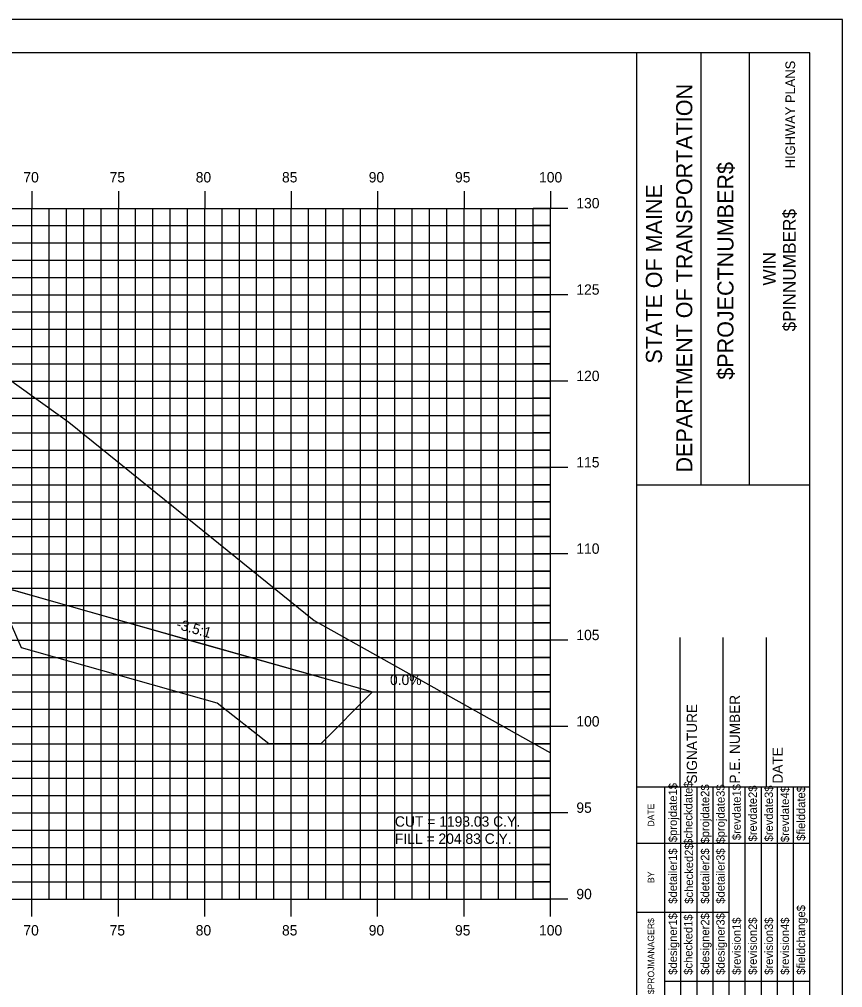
# Model space of a CAD drawing. Extents: x 850598 to 870284, y 366541 to 366651.
# Drawn here: x 854268.3 to 854315.9, y 366595.1 to 366651.2 of the extents above; entities that cross this region are included whole.
import ezdxf

# ---------------------------------------------------------------- set-up
doc = ezdxf.new("R2010")
doc.units = 0
for name, color, linetype in [('ANNOTATION', 7, 'Continuous'), ('BORDER', 7, 'Continuous'), ('D_Drainage_RipRap', 7, 'Continuous'), ('D_Roadway_Centerline', 7, 'Continuous'), ('D_Roadway_SlopeLines', 7, 'Continuous'), ('D_Text_Standard', 7, 'Continuous'), ('H_V ANNOTATION', 7, 'Continuous'), ('HIGHWAY_TITLE', 7, 'Continuous'), ('MAJOR', 7, 'Continuous'), ('MINOR', 7, 'Continuous'), ('PLOT BOUNDARY', 7, 'Continuous'), ('S_Roadway_Centerline', 7, 'Continuous')]:
    doc.layers.add(name, color=color, linetype=linetype)

msp = doc.modelspace()

# ---------------------------------------------------------------- linework, layer by layer
at = {"layer": 'BORDER'}
for p, q in [((854314.002, 366649.225), (854154.002, 366649.225)), ((854304.002, 366544.225), (854304.002, 366649.225)), ((854307.73, 366624.222), (854307.73, 366649.222)), ((854310.525, 366624.222), (854310.525, 366649.222)), ((854314.002, 366544.225), (854314.002, 366649.225)), ((854304.003, 366624.219), (854314.002, 366624.219)), ((854306.502, 366606.728), (854306.502, 366615.376)), ((854309.002, 366606.728), (854309.002, 366615.376)), ((854311.502, 366606.728), (854311.502, 366615.376)), ((854304.002, 366606.728), (854314.002, 366606.728))]:
    msp.add_line(p, q, dxfattribs=at)
for points in [[(854305.617, 366603.478), (854305.617, 366606.728)], [(854306.549, 366589.231), (854306.549, 366606.728)], [(854307.481, 366606.728), (854307.481, 366589.231)], [(854308.413, 366589.231), (854308.413, 366606.728)], [(854309.344, 366589.231), (854309.344, 366606.728)], [(854310.276, 366589.231), (854310.276, 366606.728)], [(854311.208, 366589.231), (854311.208, 366606.728)], [(854312.139, 366589.231), (854312.139, 366606.728)], [(854313.071, 366589.231), (854313.071, 366606.728)], [(854305.618, 366589.231), (854305.618, 366606.022)], [(854304.002, 366603.478), (854314.002, 366603.478)], [(854304.002, 366599.478), (854305.618, 366599.478)], [(854305.617, 366599.478), (854309.343, 366599.478)], [(854305.617, 366595.478), (854314.002, 366595.478)]]:
    msp.add_lwpolyline(points, dxfattribs=at)
at = {"layer": 'D_Drainage_RipRap'}
msp.add_lwpolyline([(854267.538, 366618.225), (854278.852, 366615.02), (854288.714, 366612.225), (854285.714, 366609.225), (854282.714, 366609.225), (854279.714, 366611.57), (854268.4, 366614.775), (854267.538, 366616.725), (854222.002, 366629.628), (854222.002, 366631.128)], close=True, dxfattribs=at)
at = {"layer": 'D_Roadway_Centerline'}
msp.add_lwpolyline([(854168.892, 366628.211), (854174.002, 366629.914), (854177.804, 366631.182), (854184.002, 366633.248), (854188.002, 366633.488), (854199.002, 366633.818), (854210.002, 366633.488), (854214.002, 366633.248), (854216.002, 366633.128), (854222.002, 366631.128), (854267.538, 366618.225), (854278.852, 366615.02), (854288.714, 366612.225), (854292.714, 366612.225)], dxfattribs=at)
at = {"layer": 'D_Roadway_SlopeLines'}
msp.add_lwpolyline([(854222.002, 366631.128), (854288.714, 366612.225), (854288.714, 366612.225)], dxfattribs=at)
at = {"layer": 'MAJOR'}
for p, q in [((854269.002, 366641.227), (854269.002, 366640.225)), ((854269.002, 366641.227), (854269.002, 366640.225)), ((854274.002, 366641.227), (854274.002, 366640.225)), ((854274.002, 366641.227), (854274.002, 366640.225)), ((854279.002, 366641.227), (854279.002, 366640.225)), ((854279.002, 366641.227), (854279.002, 366640.225)), ((854284.002, 366641.227), (854284.002, 366640.225)), ((854284.002, 366641.227), (854284.002, 366640.225)), ((854289.002, 366641.227), (854289.002, 366640.225)), ((854289.002, 366641.227), (854289.002, 366640.225)), ((854294.002, 366641.227), (854294.002, 366640.225)), ((854294.002, 366641.227), (854294.002, 366640.225)), ((854299.002, 366641.227), (854299.002, 366640.225)), ((854299.002, 366641.227), (854299.002, 366640.225)), ((854159.002, 366640.225), (854299.002, 366640.225)), ((854159.002, 366640.225), (854299.002, 366640.225)), ((854159.002, 366640.225), (854299.002, 366640.225)), ((854159.002, 366640.225), (854299.002, 366640.225)), ((854269.002, 366600.225), (854269.002, 366640.225)), ((854269.002, 366600.225), (854269.002, 366640.225)), ((854274.002, 366600.225), (854274.002, 366640.225)), ((854274.002, 366600.225), (854274.002, 366640.225)), ((854279.002, 366600.225), (854279.002, 366640.225)), ((854279.002, 366600.225), (854279.002, 366640.225)), ((854284.002, 366600.225), (854284.002, 366640.225)), ((854284.002, 366600.225), (854284.002, 366640.225)), ((854289.002, 366600.225), (854289.002, 366640.225)), ((854289.002, 366600.225), (854289.002, 366640.225)), ((854294.002, 366600.225), (854294.002, 366640.225)), ((854294.002, 366600.225), (854294.002, 366640.225)), ((854300.004, 366640.225), (854298, 366640.225)), ((854300.004, 366640.225), (854298, 366640.225)), ((854299.002, 366600.225), (854299.002, 366640.225)), ((854299.002, 366600.225), (854299.002, 366640.225)), ((854299.002, 366600.225), (854299.002, 366640.225)), ((854299.002, 366600.225), (854299.002, 366640.225)), ((854159.002, 366635.225), (854299.002, 366635.225)), ((854159.002, 366635.225), (854299.002, 366635.225)), ((854300.004, 366635.225), (854298, 366635.225)), ((854300.004, 366635.225), (854298, 366635.225)), ((854159.002, 366630.225), (854299.002, 366630.225)), ((854159.002, 366630.225), (854299.002, 366630.225)), ((854300.004, 366630.225), (854298, 366630.225)), ((854300.004, 366630.225), (854298, 366630.225)), ((854159.002, 366625.225), (854299.002, 366625.225)), ((854159.002, 366625.225), (854299.002, 366625.225)), ((854300.004, 366625.225), (854298, 366625.225)), ((854300.004, 366625.225), (854298, 366625.225)), ((854159.002, 366620.225), (854299.002, 366620.225)), ((854159.002, 366620.225), (854299.002, 366620.225)), ((854300.004, 366620.225), (854298, 366620.225)), ((854300.004, 366620.225), (854298, 366620.225)), ((854159.002, 366615.225), (854299.002, 366615.225)), ((854159.002, 366615.225), (854299.002, 366615.225)), ((854300.004, 366615.225), (854298, 366615.225)), ((854300.004, 366615.225), (854298, 366615.225)), ((854159.002, 366610.225), (854299.002, 366610.225)), ((854159.002, 366610.225), (854299.002, 366610.225)), ((854300.004, 366610.225), (854298, 366610.225)), ((854300.004, 366610.225), (854298, 366610.225)), ((854159.002, 366605.225), (854299.002, 366605.225)), ((854159.002, 366605.225), (854299.002, 366605.225)), ((854300.004, 366605.225), (854298, 366605.225)), ((854300.004, 366605.225), (854298, 366605.225)), ((854159.002, 366600.225), (854299.002, 366600.225)), ((854159.002, 366600.225), (854299.002, 366600.225)), ((854159.002, 366600.225), (854299.002, 366600.225)), ((854159.002, 366600.225), (854299.002, 366600.225)), ((854269.002, 366599.223), (854269.002, 366600.225)), ((854269.002, 366599.223), (854269.002, 366600.225)), ((854274.002, 366599.223), (854274.002, 366600.225)), ((854274.002, 366599.223), (854274.002, 366600.225)), ((854279.002, 366599.223), (854279.002, 366600.225)), ((854279.002, 366599.223), (854279.002, 366600.225)), ((854284.002, 366599.223), (854284.002, 366600.225)), ((854284.002, 366599.223), (854284.002, 366600.225)), ((854289.002, 366599.223), (854289.002, 366600.225)), ((854289.002, 366599.223), (854289.002, 366600.225)), ((854294.002, 366599.223), (854294.002, 366600.225)), ((854294.002, 366599.223), (854294.002, 366600.225)), ((854300.004, 366600.225), (854298, 366600.225)), ((854300.004, 366600.225), (854298, 366600.225)), ((854299.002, 366599.223), (854299.002, 366600.225)), ((854299.002, 366599.223), (854299.002, 366600.225))]:
    msp.add_line(p, q, dxfattribs=at)
at = {"layer": 'MINOR'}
for p, q in [((854270.002, 366600.225), (854270.002, 366640.225)), ((854270.002, 366600.225), (854270.002, 366640.225)), ((854271.002, 366600.225), (854271.002, 366640.225)), ((854271.002, 366600.225), (854271.002, 366640.225)), ((854272.002, 366600.225), (854272.002, 366640.225)), ((854272.002, 366600.225), (854272.002, 366640.225)), ((854273.002, 366600.225), (854273.002, 366640.225)), ((854273.002, 366600.225), (854273.002, 366640.225)), ((854275.002, 366600.225), (854275.002, 366640.225)), ((854275.002, 366600.225), (854275.002, 366640.225)), ((854276.002, 366600.225), (854276.002, 366640.225)), ((854276.002, 366600.225), (854276.002, 366640.225)), ((854277.002, 366600.225), (854277.002, 366640.225)), ((854277.002, 366600.225), (854277.002, 366640.225)), ((854278.002, 366600.225), (854278.002, 366640.225)), ((854278.002, 366600.225), (854278.002, 366640.225)), ((854280.002, 366600.225), (854280.002, 366640.225)), ((854280.002, 366600.225), (854280.002, 366640.225)), ((854281.002, 366600.225), (854281.002, 366640.225)), ((854281.002, 366600.225), (854281.002, 366640.225)), ((854282.002, 366600.225), (854282.002, 366640.225)), ((854282.002, 366600.225), (854282.002, 366640.225)), ((854283.002, 366600.225), (854283.002, 366640.225)), ((854283.002, 366600.225), (854283.002, 366640.225)), ((854285.002, 366600.225), (854285.002, 366640.225)), ((854285.002, 366600.225), (854285.002, 366640.225)), ((854286.002, 366600.225), (854286.002, 366640.225)), ((854286.002, 366600.225), (854286.002, 366640.225)), ((854287.002, 366600.225), (854287.002, 366640.225)), ((854287.002, 366600.225), (854287.002, 366640.225)), ((854288.002, 366600.225), (854288.002, 366640.225)), ((854288.002, 366600.225), (854288.002, 366640.225)), ((854290.002, 366600.225), (854290.002, 366640.225)), ((854290.002, 366600.225), (854290.002, 366640.225)), ((854291.002, 366600.225), (854291.002, 366640.225)), ((854291.002, 366600.225), (854291.002, 366640.225)), ((854292.002, 366600.225), (854292.002, 366640.225)), ((854292.002, 366600.225), (854292.002, 366640.225)), ((854293.002, 366600.225), (854293.002, 366640.225)), ((854293.002, 366600.225), (854293.002, 366640.225)), ((854295.002, 366600.225), (854295.002, 366640.225)), ((854295.002, 366600.225), (854295.002, 366640.225)), ((854296.002, 366600.225), (854296.002, 366640.225)), ((854296.002, 366600.225), (854296.002, 366640.225)), ((854297.002, 366600.225), (854297.002, 366640.225)), ((854297.002, 366600.225), (854297.002, 366640.225)), ((854298.002, 366600.225), (854298.002, 366640.225)), ((854298.002, 366600.225), (854298.002, 366640.225)), ((854159.002, 366639.225), (854299.002, 366639.225)), ((854159.002, 366639.225), (854299.002, 366639.225)), ((854299.002, 366639.225), (854298, 366639.225)), ((854299.002, 366639.225), (854298, 366639.225)), ((854159.002, 366638.225), (854299.002, 366638.225)), ((854159.002, 366638.225), (854299.002, 366638.225)), ((854299.002, 366638.225), (854298, 366638.225)), ((854299.002, 366638.225), (854298, 366638.225)), ((854159.002, 366637.225), (854299.002, 366637.225)), ((854159.002, 366637.225), (854299.002, 366637.225)), ((854299.002, 366637.225), (854298, 366637.225)), ((854299.002, 366637.225), (854298, 366637.225)), ((854159.002, 366636.225), (854299.002, 366636.225)), ((854159.002, 366636.225), (854299.002, 366636.225)), ((854299.002, 366636.225), (854298, 366636.225)), ((854299.002, 366636.225), (854298, 366636.225)), ((854159.002, 366634.225), (854299.002, 366634.225)), ((854159.002, 366634.225), (854299.002, 366634.225)), ((854299.002, 366634.225), (854298, 366634.225)), ((854299.002, 366634.225), (854298, 366634.225)), ((854159.002, 366633.225), (854299.002, 366633.225)), ((854159.002, 366633.225), (854299.002, 366633.225)), ((854299.002, 366633.225), (854298, 366633.225)), ((854299.002, 366633.225), (854298, 366633.225)), ((854159.002, 366632.225), (854299.002, 366632.225)), ((854159.002, 366632.225), (854299.002, 366632.225)), ((854299.002, 366632.225), (854298, 366632.225)), ((854299.002, 366632.225), (854298, 366632.225)), ((854159.002, 366631.225), (854299.002, 366631.225)), ((854159.002, 366631.225), (854299.002, 366631.225)), ((854299.002, 366631.225), (854298, 366631.225)), ((854299.002, 366631.225), (854298, 366631.225)), ((854159.002, 366629.225), (854299.002, 366629.225)), ((854159.002, 366629.225), (854299.002, 366629.225)), ((854299.002, 366629.225), (854298, 366629.225)), ((854299.002, 366629.225), (854298, 366629.225)), ((854159.002, 366628.225), (854299.002, 366628.225)), ((854159.002, 366628.225), (854299.002, 366628.225)), ((854299.002, 366628.225), (854298, 366628.225)), ((854299.002, 366628.225), (854298, 366628.225)), ((854159.002, 366627.225), (854299.002, 366627.225)), ((854159.002, 366627.225), (854299.002, 366627.225)), ((854299.002, 366627.225), (854298, 366627.225)), ((854299.002, 366627.225), (854298, 366627.225)), ((854159.002, 366626.225), (854299.002, 366626.225)), ((854159.002, 366626.225), (854299.002, 366626.225)), ((854299.002, 366626.225), (854298, 366626.225)), ((854299.002, 366626.225), (854298, 366626.225)), ((854159.002, 366624.225), (854299.002, 366624.225)), ((854159.002, 366624.225), (854299.002, 366624.225)), ((854299.002, 366624.225), (854298, 366624.225)), ((854299.002, 366624.225), (854298, 366624.225)), ((854159.002, 366623.225), (854299.002, 366623.225)), ((854159.002, 366623.225), (854299.002, 366623.225)), ((854299.002, 366623.225), (854298, 366623.225)), ((854299.002, 366623.225), (854298, 366623.225)), ((854159.002, 366622.225), (854299.002, 366622.225)), ((854159.002, 366622.225), (854299.002, 366622.225)), ((854299.002, 366622.225), (854298, 366622.225)), ((854299.002, 366622.225), (854298, 366622.225)), ((854159.002, 366621.225), (854299.002, 366621.225)), ((854159.002, 366621.225), (854299.002, 366621.225)), ((854299.002, 366621.225), (854298, 366621.225)), ((854299.002, 366621.225), (854298, 366621.225)), ((854159.002, 366619.225), (854299.002, 366619.225)), ((854159.002, 366619.225), (854299.002, 366619.225)), ((854299.002, 366619.225), (854298, 366619.225)), ((854299.002, 366619.225), (854298, 366619.225)), ((854159.002, 366618.225), (854299.002, 366618.225)), ((854159.002, 366618.225), (854299.002, 366618.225)), ((854299.002, 366618.225), (854298, 366618.225)), ((854299.002, 366618.225), (854298, 366618.225)), ((854159.002, 366617.225), (854299.002, 366617.225)), ((854159.002, 366617.225), (854299.002, 366617.225)), ((854299.002, 366617.225), (854298, 366617.225)), ((854299.002, 366617.225), (854298, 366617.225)), ((854159.002, 366616.225), (854299.002, 366616.225)), ((854159.002, 366616.225), (854299.002, 366616.225)), ((854299.002, 366616.225), (854298, 366616.225)), ((854299.002, 366616.225), (854298, 366616.225)), ((854159.002, 366614.225), (854299.002, 366614.225)), ((854159.002, 366614.225), (854299.002, 366614.225)), ((854299.002, 366614.225), (854298, 366614.225)), ((854299.002, 366614.225), (854298, 366614.225)), ((854159.002, 366613.225), (854299.002, 366613.225)), ((854159.002, 366613.225), (854299.002, 366613.225)), ((854299.002, 366613.225), (854298, 366613.225)), ((854299.002, 366613.225), (854298, 366613.225)), ((854159.002, 366612.225), (854299.002, 366612.225)), ((854159.002, 366612.225), (854299.002, 366612.225)), ((854299.002, 366612.225), (854298, 366612.225)), ((854299.002, 366612.225), (854298, 366612.225)), ((854159.002, 366611.225), (854299.002, 366611.225)), ((854159.002, 366611.225), (854299.002, 366611.225)), ((854299.002, 366611.225), (854298, 366611.225)), ((854299.002, 366611.225), (854298, 366611.225)), ((854159.002, 366609.225), (854299.002, 366609.225)), ((854159.002, 366609.225), (854299.002, 366609.225)), ((854299.002, 366609.225), (854298, 366609.225)), ((854299.002, 366609.225), (854298, 366609.225)), ((854159.002, 366608.225), (854299.002, 366608.225)), ((854159.002, 366608.225), (854299.002, 366608.225)), ((854299.002, 366608.225), (854298, 366608.225)), ((854299.002, 366608.225), (854298, 366608.225)), ((854159.002, 366607.225), (854299.002, 366607.225)), ((854159.002, 366607.225), (854299.002, 366607.225)), ((854299.002, 366607.225), (854298, 366607.225)), ((854299.002, 366607.225), (854298, 366607.225)), ((854159.002, 366606.225), (854299.002, 366606.225)), ((854159.002, 366606.225), (854299.002, 366606.225)), ((854299.002, 366606.225), (854298, 366606.225)), ((854299.002, 366606.225), (854298, 366606.225)), ((854159.002, 366604.225), (854299.002, 366604.225)), ((854159.002, 366604.225), (854299.002, 366604.225)), ((854299.002, 366604.225), (854298, 366604.225)), ((854299.002, 366604.225), (854298, 366604.225)), ((854159.002, 366603.225), (854299.002, 366603.225)), ((854159.002, 366603.225), (854299.002, 366603.225)), ((854299.002, 366603.225), (854298, 366603.225)), ((854299.002, 366603.225), (854298, 366603.225)), ((854159.002, 366602.225), (854299.002, 366602.225)), ((854159.002, 366602.225), (854299.002, 366602.225)), ((854299.002, 366602.225), (854298, 366602.225)), ((854299.002, 366602.225), (854298, 366602.225)), ((854159.002, 366601.225), (854299.002, 366601.225)), ((854159.002, 366601.225), (854299.002, 366601.225)), ((854299.002, 366601.225), (854298, 366601.225)), ((854299.002, 366601.225), (854298, 366601.225))]:
    msp.add_line(p, q, dxfattribs=at)
at = {"layer": 'PLOT BOUNDARY'}
msp.add_lwpolyline([(854145.908, 366541.166), (854315.908, 366541.166), (854315.908, 366651.166), (854145.908, 366651.166)], close=True, dxfattribs=at)
at = {"layer": 'S_Roadway_Centerline'}
msp.add_lwpolyline([(854159.002, 366627.839), (854216.63, 366630.01), (854218.775, 366630.215), (854220.627, 366630.275), (854225.39, 366631.244), (854228.119, 366631.812), (854228.488, 366631.926), (854231.762, 366632.636), (854243.689, 366633.11), (854247.064, 366633.263), (854250.093, 366633.142), (854260.781, 366632.431), (854262.602, 366632.508), (854263.09, 366632.478), (854266.237, 366631.107), (854266.87, 366630.899), (854271.128, 366627.838), (854285.333, 366616.357), (854299.002, 366608.705)], dxfattribs=at)

# ---------------------------------------------------------------- texts
at = {"layer": 'ANNOTATION'}
msp.add_text('-3.5:1', height=0.6, rotation=344.1804, dxfattribs=at).set_placement((854277.311, 366615.896))
msp.add_text('0.0%', height=0.6, dxfattribs=at).set_placement((854289.718, 366612.625))
at = {"layer": 'BORDER'}
for s, height, p in [('DEPARTMENT OF TRANSPORTATION', 0.93176, (854307.209, 366624.931)), ('$PROJECTNUMBER$', 0.93176, (854309.594, 366630.304)), ('STATE OF MAINE', 0.93176, (854305.457, 366631.237)), ('$PINNUMBER$', 0.74527, (854313.197, 366633.1)), ('WIN', 0.7453, (854312.039, 366635.755)), ('SIGNATURE', 0.5906, (854307.482, 366606.92)), ('P.E. NUMBER', 0.59055, (854309.963, 366606.92)), ('DATE', 0.5906, (854312.443, 366606.92)), ('$checkdate$', 0.48455, (854307.219, 366603.371)), ('$projdate1$', 0.48455, (854306.325, 366603.529)), ('$projdate2$', 0.48455, (854308.188, 366603.45)), ('$projdate3$', 0.48455, (854309.083, 366603.45)), ('$revdate1$', 0.4845, (854310.014, 366603.647)), ('$revdate2$', 0.4845, (854310.946, 366603.568)), ('$revdate3$', 0.4845, (854311.878, 366603.568)), ('$revdate4$', 0.4845, (854312.809, 366603.529)), ('$fielddate$', 0.48455, (854313.741, 366603.607)), ('DATE', 0.3714, (854305.006, 366604.434)), ('$detailer1$', 0.48455, (854306.325, 366599.963)), ('$checked2$', 0.4845, (854307.256, 366599.963)), ('$detailer2$', 0.48455, (854308.188, 366599.963)), ('$detailer3$', 0.48455, (854309.083, 366599.963)), ('BY', 0.3714, (854305.006, 366601.163)), ('$fieldchange$', 0.48455, (854313.741, 366595.851)), ('$designer1$', 0.48455, (854306.325, 366595.851)), ('$checked1$', 0.4845, (854307.219, 366595.851)), ('$designer2$', 0.48455, (854308.188, 366595.851)), ('$designer3$', 0.48455, (854309.083, 366595.851)), ('$revision1$', 0.48455, (854310.014, 366595.851)), ('$revision2$', 0.48455, (854310.946, 366595.851)), ('$revision3$', 0.48455, (854311.878, 366595.851)), ('$revision4$', 0.48455, (854312.809, 366595.851)), ('$PROJMANAGER$', 0.37275, (854305.006, 366594.723))]:
    msp.add_text(s, height=height, rotation=90, dxfattribs=at).set_placement(p)
at = {"layer": 'D_Text_Standard'}
for s, p in [('CUT = 1193.03 C.Y.', (854290.002, 366604.425)), ('FILL = 204.83 C.Y.', (854290.002, 366603.429))]:
    msp.add_text(s, height=0.6, dxfattribs=at).set_placement(p)
at = {"layer": 'H_V ANNOTATION'}
for s, p in [('70', (854268.504, 366641.725)), ('75', (854273.496, 366641.725)), ('80', (854278.477, 366641.725)), ('85', (854283.469, 366641.725)), ('90', (854288.488, 366641.725)), ('95', (854293.48, 366641.725)), ('100', (854298.343, 366641.725)), ('130', (854300.502, 366640.225)), ('125', (854300.502, 366635.225)), ('120', (854300.502, 366630.225)), ('115', (854300.502, 366625.225)), ('110', (854300.502, 366620.225)), ('105', (854300.502, 366615.225)), ('100', (854300.502, 366610.225)), ('95', (854300.502, 366605.225)), ('90', (854300.502, 366600.225)), ('70', (854268.504, 366598.125)), ('75', (854273.496, 366598.125)), ('80', (854278.477, 366598.125)), ('85', (854283.469, 366598.125)), ('90', (854288.488, 366598.125)), ('95', (854293.48, 366598.125)), ('100', (854298.343, 366598.125))]:
    msp.add_text(s, height=0.6, dxfattribs=at).set_placement(p)
at = {"layer": 'HIGHWAY_TITLE'}
msp.add_text('HIGHWAY PLANS', height=0.55901, rotation=90, dxfattribs=at).set_placement((854313.16, 366642.541))

doc.saveas('drawing.dxf')
